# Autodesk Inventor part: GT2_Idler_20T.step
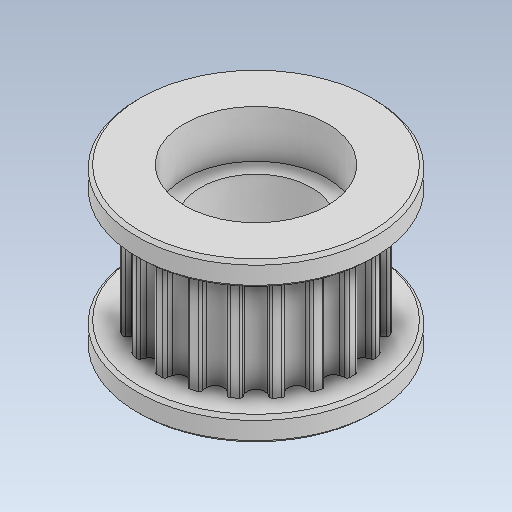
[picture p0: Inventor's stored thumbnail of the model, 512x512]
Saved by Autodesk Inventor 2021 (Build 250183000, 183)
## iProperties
Created: 2023-10
Part Number: GT2_Idler_20T.step
Material: Generico
Document SubType Name: Modeling
Designer: hp
Density: 1 g/cm^3
Appearance: Default
Author: hp
Revision Number: ANY
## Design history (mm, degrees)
feature "Solido1"
body "Solid1"
